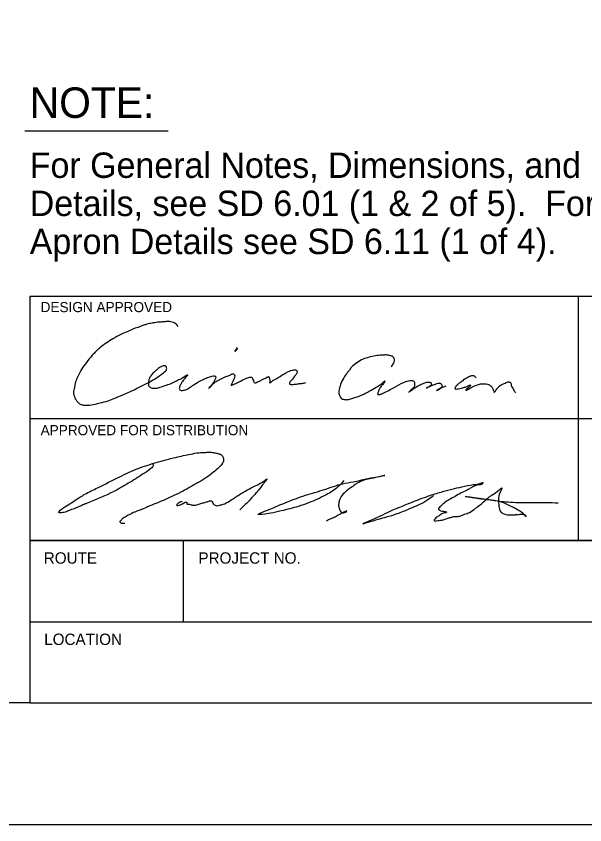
# Model space of a CAD drawing. Extents: x -0.08 to 2.83, y -0.03 to 1.92.
# Drawn here: x 2.0669 to 2.3584, y 0 to 0.4144 of the extents above; entities that cross this region are included whole.
import ezdxf

# ---------------------------------------------------------------- set-up
doc = ezdxf.new("R2010")
doc.units = 0
for name, color, linetype in [('55', 7, 'Continuous'), ('57', 7, 'Continuous'), ('63', 7, 'Continuous')]:
    doc.layers.add(name, color=color, linetype=linetype)

msp = doc.modelspace()

# ---------------------------------------------------------------- linework, layer by layer
at = {"layer": '55'}
for points in [[(2.1500069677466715, 0.25542621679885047), (2.147577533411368, 0.2574101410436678), (2.1461672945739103, 0.2578491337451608), (2.1442302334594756, 0.2579375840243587), (2.1422467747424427, 0.25775571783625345), (2.140196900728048, 0.2576109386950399), (2.1372155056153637, 0.25720220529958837), (2.134606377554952, 0.2567424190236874), (2.1331233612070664, 0.25633337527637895), (2.1313915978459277, 0.25569730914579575), (2.130904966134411, 0.2554811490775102), (2.1278956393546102, 0.254460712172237), (2.1248414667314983, 0.2532039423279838), (2.1206008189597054, 0.2513202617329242), (2.1164790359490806, 0.24905655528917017), (2.112972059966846, 0.24683288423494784), (2.109866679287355, 0.24445465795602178), (2.1058774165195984, 0.24061839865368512), (2.1029880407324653, 0.2370043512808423), (2.1005930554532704, 0.23377638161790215), (2.0985717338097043, 0.22978215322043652), (2.097353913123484, 0.22697719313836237), (2.096580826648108, 0.22347083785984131), (2.0963238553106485, 0.22082632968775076), (2.096499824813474, 0.22020531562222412), (2.096808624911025, 0.2195101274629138), (2.097231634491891, 0.21833296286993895), (2.0979975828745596, 0.21720824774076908), (2.0993643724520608, 0.21581771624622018), (2.101004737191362, 0.21519794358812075), (2.1035519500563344, 0.21504757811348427), (2.1073598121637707, 0.21565695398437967), (2.1099411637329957, 0.2162542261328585), (2.113988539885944, 0.21726131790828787), (2.1174574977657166, 0.2186523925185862), (2.12240256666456, 0.22067417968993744), (2.128578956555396, 0.22355921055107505), (2.134136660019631, 0.22631924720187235), (2.1412178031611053, 0.2307464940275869), (2.1435522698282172, 0.23264910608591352), (2.143802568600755, 0.2329101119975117), (2.1440344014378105, 0.23351250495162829), (2.144034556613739, 0.23426169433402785), (2.1439512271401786, 0.23467415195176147), (2.1436624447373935, 0.2350619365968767), (2.143056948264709, 0.2352258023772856), (2.142306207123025, 0.2351919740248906), (2.1413762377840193, 0.23496200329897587), (2.1401480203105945, 0.23416672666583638), (2.138306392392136, 0.232616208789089), (2.136596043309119, 0.23095753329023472), (2.1355020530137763, 0.2293728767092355), (2.134851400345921, 0.22780203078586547), (2.1346858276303, 0.22641336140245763), (2.1347103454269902, 0.22545871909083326), (2.134988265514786, 0.22483304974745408), (2.1355087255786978, 0.2242984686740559), (2.136138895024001, 0.22392914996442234), (2.1371197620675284, 0.22378219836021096), (2.13865212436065, 0.22378033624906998), (2.1406140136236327, 0.22423562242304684), (2.1439014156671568, 0.22537957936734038), (2.1470884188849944, 0.22656217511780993), (2.1496359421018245, 0.22791018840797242), (2.1523502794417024, 0.2291824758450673), (2.154800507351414, 0.23063709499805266), (2.153210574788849, 0.22863237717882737), (2.1527794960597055, 0.22814124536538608), (2.1521227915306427, 0.22718365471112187), (2.1512373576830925, 0.22569163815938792), (2.150548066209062, 0.2240203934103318), (2.1506158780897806, 0.2232681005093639), (2.151134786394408, 0.2226995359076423), (2.151710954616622, 0.22263917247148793), (2.153527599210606, 0.2228967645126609), (2.154917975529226, 0.22351436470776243), (2.1573064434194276, 0.2251080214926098), (2.159972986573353, 0.22682519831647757), (2.1627630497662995, 0.22826429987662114), (2.1651266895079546, 0.22931422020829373), (2.1671998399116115, 0.22996875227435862), (2.1687692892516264, 0.23003330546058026), (2.1688534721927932, 0.23001243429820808), (2.1690542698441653, 0.22993515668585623), (2.1691631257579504, 0.22970883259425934), (2.1692093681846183, 0.22922995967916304), (2.1690161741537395, 0.2287279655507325), (2.1684628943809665, 0.22742510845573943), (2.1677033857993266, 0.2260805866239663), (2.1656932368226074, 0.22382262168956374), (2.166277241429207, 0.22430677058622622), (2.168280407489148, 0.22641180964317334), (2.1688257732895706, 0.22679555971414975), (2.169879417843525, 0.2274966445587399), (2.171099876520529, 0.22812200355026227), (2.1728085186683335, 0.22899750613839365), (2.174548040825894, 0.22980348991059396), (2.176522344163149, 0.23053064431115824), (2.178045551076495, 0.23107407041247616), (2.178450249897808, 0.23098748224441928), (2.1788394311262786, 0.23056105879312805), (2.1788577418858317, 0.22947048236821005), (2.1783129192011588, 0.22797993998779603), (2.1779551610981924, 0.22723005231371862), (2.1773099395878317, 0.2257781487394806), (2.177159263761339, 0.2254615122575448), (2.177155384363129, 0.2253765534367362), (2.1775307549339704, 0.22539346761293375), (2.1782066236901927, 0.2256520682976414), (2.1789527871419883, 0.22595854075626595), (2.1800318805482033, 0.22647116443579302), (2.18113184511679, 0.22706797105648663), (2.184247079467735, 0.22854330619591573), (2.185947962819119, 0.2292488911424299), (2.187013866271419, 0.22947265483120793), (2.187506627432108, 0.22945015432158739), (2.1876394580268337, 0.2293759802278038), (2.187770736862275, 0.22926782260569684), (2.1880548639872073, 0.2287780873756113), (2.188485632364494, 0.22777084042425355), (2.189192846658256, 0.22647853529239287), (2.1902973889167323, 0.22680269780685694), (2.1916197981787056, 0.22742340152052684), (2.193050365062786, 0.2281753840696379), (2.1947219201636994, 0.2289844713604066), (2.19580334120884, 0.2295480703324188), (2.1961849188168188, 0.22970091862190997), (2.196515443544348, 0.22948149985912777), (2.1967655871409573, 0.22899331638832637), (2.1968118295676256, 0.22851444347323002), (2.196882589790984, 0.22708092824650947), (2.196891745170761, 0.22653564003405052), (2.1969921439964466, 0.22649700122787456), (2.1979407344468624, 0.22713477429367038), (2.200537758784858, 0.228821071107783), (2.203062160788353, 0.23040852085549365), (2.2051616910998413, 0.23164077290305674), (2.2069738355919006, 0.23254560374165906), (2.208390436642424, 0.2329917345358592), (2.2100649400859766, 0.2331195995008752), (2.210599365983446, 0.23289087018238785), (2.2108186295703, 0.23247220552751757), (2.210898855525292, 0.23199178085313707), (2.2108091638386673, 0.23151911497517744), (2.2104043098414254, 0.23085651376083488), (2.2096456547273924, 0.22990357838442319), (2.208306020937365, 0.22815986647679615), (2.2071193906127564, 0.22678376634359), (2.2069895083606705, 0.22617671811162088), (2.2071454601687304, 0.22586310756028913), (2.208498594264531, 0.22566510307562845), (2.2094223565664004, 0.22575913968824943), (2.210551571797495, 0.2258778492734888), (2.211614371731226, 0.22603364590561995), (2.212471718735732, 0.22616476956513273), (2.2141833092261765, 0.2263590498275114), (2.2153898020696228, 0.22667855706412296)], [(2.1798599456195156, 0.2447066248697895), (2.1799895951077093, 0.24418988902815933), (2.179454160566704, 0.24327784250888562), (2.178909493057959, 0.2425364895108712), (2.180163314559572, 0.24389249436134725), (2.180611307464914, 0.24400825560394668)], [(2.2591252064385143, 0.2347190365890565), (2.2602902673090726, 0.23636855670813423), (2.260761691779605, 0.23774326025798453), (2.2607649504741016, 0.23856041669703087), (2.2606198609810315, 0.23911191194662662), (2.260043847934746, 0.23992146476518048), (2.259446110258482, 0.24025524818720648), (2.2583030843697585, 0.24057987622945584), (2.256440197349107, 0.24080115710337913), (2.2542219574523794, 0.24069812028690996), (2.2511432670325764, 0.24039599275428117), (2.2477709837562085, 0.2396305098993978), (2.244797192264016, 0.23864250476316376), (2.2415482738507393, 0.2368497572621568), (2.2388213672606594, 0.23455641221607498), (2.2376964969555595, 0.23304127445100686), (2.2365036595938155, 0.23152924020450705), (2.2348240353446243, 0.2290518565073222), (2.2331689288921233, 0.22561983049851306), (2.2325103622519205, 0.22312987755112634), (2.232303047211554, 0.2215728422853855), (2.232497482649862, 0.22061044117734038), (2.2327545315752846, 0.21990058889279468), (2.233335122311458, 0.2188183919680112), (2.234140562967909, 0.21818566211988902), (2.234983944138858, 0.21801093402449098), (2.236102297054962, 0.21789175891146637), (2.2369565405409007, 0.21795491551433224), (2.2378138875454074, 0.21808603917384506), (2.238987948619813, 0.21844108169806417), (2.241062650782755, 0.21912959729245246), (2.2433829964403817, 0.21997716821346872), (2.245680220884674, 0.22106417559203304), (2.2479125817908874, 0.22222225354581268), (2.2514813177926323, 0.22430688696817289), (2.254075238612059, 0.22592521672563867), (2.2552818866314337, 0.22699391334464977), (2.2559555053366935, 0.22757613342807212), (2.2558040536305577, 0.22724250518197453), (2.2556912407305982, 0.22700927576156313), (2.2544211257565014, 0.2252964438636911), (2.2533286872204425, 0.22374577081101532), (2.252685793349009, 0.22234484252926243), (2.252450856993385, 0.22167448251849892), (2.2522143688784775, 0.2209701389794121), (2.252205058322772, 0.22076623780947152), (2.2522652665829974, 0.22059321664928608), (2.2526344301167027, 0.22047419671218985), (2.252977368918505, 0.22052664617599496), (2.253596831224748, 0.22066863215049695), (2.2550196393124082, 0.22125069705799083), (2.2607388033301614, 0.22419066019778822), (2.2654522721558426, 0.22673383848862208), (2.267319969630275, 0.22736369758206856), (2.268767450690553, 0.2277403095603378), (2.2699908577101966, 0.22768444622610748), (2.270760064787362, 0.22737688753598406), (2.2711059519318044, 0.2267481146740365), (2.271119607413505, 0.2255555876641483), (2.2710175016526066, 0.22481105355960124), (2.270611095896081, 0.22411446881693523), (2.2681900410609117, 0.2218071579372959), (2.2709338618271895, 0.22372513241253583), (2.27398043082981, 0.22556117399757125), (2.276442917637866, 0.2265384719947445), (2.2784341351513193, 0.22689025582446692), (2.279272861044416, 0.22661357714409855), (2.279848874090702, 0.22580402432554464), (2.279768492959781, 0.22553525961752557), (2.2797607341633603, 0.22536534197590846), (2.2794115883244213, 0.22517695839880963), (2.2785989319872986, 0.22453297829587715), (2.2770648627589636, 0.22375166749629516), (2.279715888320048, 0.22512900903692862), (2.281793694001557, 0.22588549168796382), (2.2825568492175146, 0.22619118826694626), (2.284025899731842, 0.22629438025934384), (2.2846931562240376, 0.22599147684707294), (2.2851703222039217, 0.2252545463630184), (2.285145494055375, 0.22471080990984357), (2.2849214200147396, 0.22427833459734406), (2.2839295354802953, 0.22343821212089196), (2.2823537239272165, 0.222488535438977), (2.2853230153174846, 0.22412377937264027), (2.2873344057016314, 0.22491734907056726)], [(2.3026712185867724, 0.22891654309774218), (2.302339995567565, 0.22949356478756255), (2.3017978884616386, 0.2299269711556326), (2.3013113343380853, 0.2300854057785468), (2.3008008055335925, 0.23009169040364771), (2.3003211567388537, 0.23002845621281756), (2.2995657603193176, 0.22989267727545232), (2.2989400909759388, 0.2296147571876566), (2.2977512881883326, 0.2289368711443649), (2.296770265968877, 0.22833463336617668), (2.295817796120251, 0.2276119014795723), (2.294285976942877, 0.2265069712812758), (2.2932091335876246, 0.22567072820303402), (2.2921554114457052, 0.22459504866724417), (2.2918919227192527, 0.22404518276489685), (2.2918045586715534, 0.22362349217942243), (2.2918231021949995, 0.2236566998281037), (2.291985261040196, 0.22347902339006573), (2.292507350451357, 0.22335302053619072), (2.2935987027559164, 0.2233883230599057), (2.2950122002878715, 0.22376648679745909), (2.29628898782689, 0.22413386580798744), (2.2979836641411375, 0.22470351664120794), (2.299324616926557, 0.22535742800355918), (2.2995656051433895, 0.22541453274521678), (2.299764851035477, 0.22530327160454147), (2.2998111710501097, 0.22519899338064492), (2.2997508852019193, 0.22499741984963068), (2.299588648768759, 0.22480050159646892), (2.2983140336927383, 0.22373490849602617), (2.297440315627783, 0.22287236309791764), (2.2973499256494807, 0.2227573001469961), (2.2974325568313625, 0.2227024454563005), (2.2978102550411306, 0.22277033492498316), (2.2988043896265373, 0.22328683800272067), (2.3005725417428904, 0.2243469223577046), (2.3018795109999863, 0.22500238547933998), (2.3039217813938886, 0.22572643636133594), (2.3060983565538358, 0.22603570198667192), (2.3084887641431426, 0.22580736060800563), (2.309493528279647, 0.2254379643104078), (2.3103646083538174, 0.2247511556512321), (2.310914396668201, 0.22411307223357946), (2.311596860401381, 0.22265162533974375), (2.311958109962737, 0.22161349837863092), (2.312603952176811, 0.22233320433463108), (2.3133363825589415, 0.2234576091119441), (2.3143406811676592, 0.22456959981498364), (2.315820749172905, 0.22565986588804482), (2.317557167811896, 0.22639788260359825), (2.3194912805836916, 0.226990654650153), (2.3197600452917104, 0.2269102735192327), (2.3202265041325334, 0.22668464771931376), (2.320701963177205, 0.2251645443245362), (2.3212609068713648, 0.2239811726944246), (2.321890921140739, 0.22286266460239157), (2.322332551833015, 0.2220933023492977), (2.322916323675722, 0.2214536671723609)], [(2.136922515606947, 0.185159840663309), (2.1371105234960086, 0.1844864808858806), (2.1370818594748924, 0.1840234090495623), (2.136805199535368, 0.1834854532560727), (2.1358939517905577, 0.18254654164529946), (2.131948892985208, 0.17981845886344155), (2.128213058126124, 0.17737820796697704), (2.1243688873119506, 0.17504310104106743), (2.11671133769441, 0.17069363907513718), (2.1037354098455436, 0.1650190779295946), (2.102285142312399, 0.1644279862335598), (2.099987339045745, 0.1633971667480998), (2.0937609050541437, 0.16091967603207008), (2.091388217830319, 0.16013685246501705), (2.0901811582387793, 0.15994086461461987), (2.0891859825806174, 0.15985480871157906), (2.0890431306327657, 0.15988826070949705), (2.088754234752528, 0.1601686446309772), (2.0888583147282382, 0.1603481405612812), (2.089137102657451, 0.16074377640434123), (2.0900133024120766, 0.16164657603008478), (2.093607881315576, 0.16401353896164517), (2.097096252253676, 0.16634332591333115), (2.1021039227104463, 0.16940758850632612), (2.108637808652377, 0.17274378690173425), (2.119977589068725, 0.17835829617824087), (2.1292027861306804, 0.18258884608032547), (2.1386239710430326, 0.1856123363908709), (2.148761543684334, 0.18832624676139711), (2.1564234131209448, 0.19000667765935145), (2.1605411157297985, 0.190708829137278), (2.1640969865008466, 0.19090434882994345), (2.1663741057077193, 0.19093839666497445), (2.168298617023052, 0.19075364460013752), (2.1702273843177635, 0.19028425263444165), (2.171801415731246, 0.18973838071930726), (2.172450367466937, 0.18917867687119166), (2.172812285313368, 0.18877482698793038), (2.173071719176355, 0.18808474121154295), (2.173241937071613, 0.18741111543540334), (2.1732305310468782, 0.18698388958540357), (2.173168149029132, 0.1863957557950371), (2.1730497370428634, 0.1859847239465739), (2.1727207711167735, 0.18537481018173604), (2.1719537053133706, 0.18431349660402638), (2.170708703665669, 0.1830848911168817), (2.1680747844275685, 0.18073229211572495), (2.1645906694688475, 0.17811786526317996), (2.160535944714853, 0.17558387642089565), (2.15564854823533, 0.17280611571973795), (2.152454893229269, 0.17099676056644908), (2.1477549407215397, 0.16877341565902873), (2.1451217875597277, 0.1675596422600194), (2.1395713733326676, 0.1650922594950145), (2.135503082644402, 0.1634655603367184), (2.1319318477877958, 0.16191746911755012), (2.127685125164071, 0.16032368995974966), (2.1248238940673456, 0.15889297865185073), (2.122776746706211, 0.15775914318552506), (2.1218256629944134, 0.1571043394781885), (2.1213148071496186, 0.15675861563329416), (2.120858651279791, 0.1563247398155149), (2.120456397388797, 0.15585608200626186), (2.1201247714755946, 0.15542406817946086), (2.120107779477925, 0.15537043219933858), (2.120109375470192, 0.15526369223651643), (2.120200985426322, 0.15508712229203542), (2.1203642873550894, 0.1548760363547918), (2.1206157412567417, 0.15471965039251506), (2.121151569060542, 0.1545853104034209), (2.121560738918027, 0.15459142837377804), (2.1223610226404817, 0.15462118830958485), (2.1226634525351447, 0.1546257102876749)], [(2.2349098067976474, 0.17650908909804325), (2.2318638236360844, 0.1731538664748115), (2.225837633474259, 0.1691846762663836), (2.2167898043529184, 0.16499236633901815), (2.2115850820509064, 0.16320632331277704), (2.2027581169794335, 0.16090347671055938), (2.197473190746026, 0.159721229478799), (2.192926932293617, 0.15911943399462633), (2.190720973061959, 0.15908645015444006), (2.1923459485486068, 0.15989368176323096), (2.1973690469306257, 0.16192612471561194), (2.2051498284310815, 0.1651742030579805), (2.2151657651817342, 0.16888275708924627), (2.2249788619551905, 0.17187651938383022), (2.2341881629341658, 0.17479007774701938), (2.239653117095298, 0.17583266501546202), (2.246393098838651, 0.17728578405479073), (2.2531352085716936, 0.17859658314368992), (2.2557617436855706, 0.17906291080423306), (2.250051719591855, 0.17774974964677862), (2.24375994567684, 0.17607201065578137), (2.2429822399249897, 0.17572229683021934), (2.242027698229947, 0.17529876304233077), (2.2406717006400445, 0.17435320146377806), (2.2381891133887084, 0.17259006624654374), (2.235849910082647, 0.1707578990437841), (2.2335035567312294, 0.16821386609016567), (2.232811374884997, 0.16690455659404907), (2.232356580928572, 0.1651895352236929), (2.232245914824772, 0.16307039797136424), (2.2324705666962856, 0.16232641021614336), (2.2327047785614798, 0.16153808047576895), (2.233272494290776, 0.16046113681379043), (2.2337408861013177, 0.16007667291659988), (2.2342602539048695, 0.1598531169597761), (2.2351476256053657, 0.16000873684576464), (2.23578407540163, 0.16028516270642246), (2.236397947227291, 0.16088154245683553), (2.2354779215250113, 0.16052970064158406), (2.2335178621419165, 0.15952172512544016), (2.2319831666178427, 0.15862687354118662), (2.230924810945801, 0.1580060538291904), (2.2285914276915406, 0.15697470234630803), (2.227000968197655, 0.15623916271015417), (2.2260658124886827, 0.15570915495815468)], [(2.1521481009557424, 0.16533369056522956), (2.151646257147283, 0.16557530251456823), (2.15086562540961, 0.1654212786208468), (2.1497026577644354, 0.16465654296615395), (2.14917693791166, 0.16411486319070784), (2.1491811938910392, 0.1638302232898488), (2.1495046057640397, 0.16362153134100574), (2.150425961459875, 0.16388442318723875), (2.151134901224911, 0.16407296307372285), (2.1524789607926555, 0.16462687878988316), (2.153571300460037, 0.1653549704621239), (2.154032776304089, 0.16543304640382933), (2.154175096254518, 0.1654351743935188), (2.154428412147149, 0.1651542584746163), (2.1544018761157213, 0.16454886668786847), (2.154761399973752, 0.1643051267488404), (2.155437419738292, 0.1643152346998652), (2.156187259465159, 0.16414850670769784), (2.156972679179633, 0.16398231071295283), (2.1577230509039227, 0.16378000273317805), (2.1589322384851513, 0.1638336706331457), (2.1601010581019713, 0.16420702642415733), (2.1621206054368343, 0.1648066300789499), (2.164033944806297, 0.16536905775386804), (2.1656642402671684, 0.16582048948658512), (2.167119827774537, 0.16605578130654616), (2.1676700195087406, 0.16496078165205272), (2.1680359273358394, 0.16429008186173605), (2.1688967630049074, 0.16384030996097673), (2.1700411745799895, 0.16346595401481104), (2.171281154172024, 0.1638403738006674), (2.1729831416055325, 0.1642572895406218), (2.1761969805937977, 0.16590680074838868), (2.180003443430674, 0.16838369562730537), (2.1850822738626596, 0.17144902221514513), (2.190873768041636, 0.1744538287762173), (2.1936978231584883, 0.17599074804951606), (2.195582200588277, 0.17730008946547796), (2.1940804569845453, 0.17539147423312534), (2.1936083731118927, 0.17483280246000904), (2.192997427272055, 0.1740407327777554), (2.191584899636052, 0.17211565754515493), (2.1903624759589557, 0.170567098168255), (2.1880511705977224, 0.16805917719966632), (2.1862833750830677, 0.1660932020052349), (2.1836181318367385, 0.16345543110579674), (2.181637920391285, 0.16141510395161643)], [(2.280747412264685, 0.16875122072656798), (2.2779690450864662, 0.16653881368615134), (2.2736633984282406, 0.16412563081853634), (2.268253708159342, 0.16176711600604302), (2.262062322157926, 0.15932573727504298), (2.2565718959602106, 0.1576065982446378), (2.252424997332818, 0.15647695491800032), (2.2445926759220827, 0.15429574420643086), (2.249259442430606, 0.15635844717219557), (2.252618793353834, 0.15779660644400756), (2.257245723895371, 0.16014341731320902), (2.2625847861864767, 0.16246528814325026), (2.269907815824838, 0.16538623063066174), (2.278223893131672, 0.16853554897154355), (2.2848130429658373, 0.17055581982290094), (2.2903071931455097, 0.17202589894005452), (2.2953781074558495, 0.17324053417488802), (2.3010910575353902, 0.17435800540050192), (2.305879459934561, 0.17542606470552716), (2.306056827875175, 0.17546430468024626), (2.306060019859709, 0.17525082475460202), (2.3031584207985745, 0.17413980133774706), (2.3008956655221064, 0.17314509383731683), (2.2992367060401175, 0.1722305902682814), (2.298072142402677, 0.1715725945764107), (2.2950685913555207, 0.1701397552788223), (2.2918929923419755, 0.16831287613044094), (2.2890694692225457, 0.16674037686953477), (2.2867079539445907, 0.16521037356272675), (2.284529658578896, 0.16332723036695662), (2.2836529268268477, 0.16246001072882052), (2.2833396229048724, 0.16199268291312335), (2.28345221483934, 0.1616028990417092), (2.283921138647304, 0.1611828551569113), (2.2853146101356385, 0.16081222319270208), (2.28727736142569, 0.16045010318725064), (2.287491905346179, 0.16038213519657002), (2.287529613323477, 0.16024034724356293), (2.2865742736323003, 0.1598701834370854), (2.2841017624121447, 0.1586232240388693), (2.2824794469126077, 0.15763809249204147), (2.2816016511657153, 0.1568420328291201), (2.2812193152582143, 0.15623132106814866), (2.2811869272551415, 0.15601730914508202), (2.281332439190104, 0.15580595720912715), (2.282257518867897, 0.1558197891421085), (2.285170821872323, 0.15614805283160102), (2.2867299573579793, 0.1565984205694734), (2.288889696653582, 0.1573424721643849), (2.2904488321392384, 0.15779283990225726), (2.292260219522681, 0.15803345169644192), (2.2943211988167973, 0.15824220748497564), (2.2966922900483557, 0.15913177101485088), (2.2993108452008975, 0.16013179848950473), (2.3023759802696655, 0.1622061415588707), (2.3047682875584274, 0.16405689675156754), (2.3094063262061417, 0.16804091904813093), (2.3110259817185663, 0.16920395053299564), (2.314337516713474, 0.17145991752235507), (2.315813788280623, 0.17269198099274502), (2.314511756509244, 0.16932724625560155), (2.3141284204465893, 0.16640330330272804), (2.3143887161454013, 0.1632754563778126), (2.3152119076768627, 0.16058308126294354), (2.3169378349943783, 0.15939889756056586), (2.3206477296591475, 0.15881378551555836), (2.322852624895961, 0.15891792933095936), (2.3230825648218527, 0.15901033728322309), (2.3232933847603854, 0.15919142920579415), (2.3235347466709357, 0.1591149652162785), (2.323643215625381, 0.1590009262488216), (2.3246742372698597, 0.15906972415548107), (2.3256317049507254, 0.15929756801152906), (2.326988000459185, 0.1590331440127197), (2.3280416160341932, 0.1581858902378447), (2.3281674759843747, 0.15809880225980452), (2.3282472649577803, 0.1581177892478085), (2.32824606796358, 0.1581978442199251), (2.3281279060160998, 0.1583651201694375), (2.327209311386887, 0.15910762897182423), (2.3270110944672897, 0.1592737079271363), (2.3250582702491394, 0.160756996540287), (2.3239170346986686, 0.16151397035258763), (2.3203223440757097, 0.16331969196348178), (2.316272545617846, 0.16521647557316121), (2.315003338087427, 0.16560675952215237), (2.3128621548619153, 0.16600179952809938), (2.3097948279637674, 0.1664541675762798), (2.306016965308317, 0.1668247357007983), (2.302093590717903, 0.16740665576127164), (2.2990262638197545, 0.16785902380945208), (2.297312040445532, 0.16826044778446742), (2.3028739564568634, 0.1675784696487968), (2.311040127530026, 0.1664727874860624), (2.3189381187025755, 0.16545206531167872), (2.324421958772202, 0.16523156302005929), (2.330988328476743, 0.1652051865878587), (2.3431965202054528, 0.16510302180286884), (2.3447272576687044, 0.16507252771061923)]]:
    msp.add_spline(points, degree=3, dxfattribs=at)
at = {"layer": '57'}
msp.add_line((2.0713113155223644, 0.35560013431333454), (2.144774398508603, 0.35560013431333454), dxfattribs=at)
msp.add_line((2.0713113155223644, 0.35560013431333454), (2.144774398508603, 0.35560013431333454), dxfattribs=at)
at = {"layer": '63'}
for p, q in [((2.729175, 0.270775), (2.073866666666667, 0.270775)), ((2.073866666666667, 0.270775), (2.073866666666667, 0.06244166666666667)), ((2.354925, 0.270775), (2.354925, 0.14577500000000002)), ((2.073866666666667, 0.20827500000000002), (2.729175, 0.20827500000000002)), ((2.073866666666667, 0.2064666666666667), (2.073866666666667, 0.2064666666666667)), ((2.073866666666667, 0.14577500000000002), (2.729175, 0.14577500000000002)), ((2.0890750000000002, 0.145825), (2.0893083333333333, 0.145825)), ((2.152655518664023, 0.10410833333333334), (2.152655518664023, 0.14577500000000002)), ((2.237416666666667, 0.145825), (2.237416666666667, 0.145825)), ((2.073866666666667, 0.1439666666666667), (2.073866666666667, 0.1439666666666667)), ((2.073866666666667, 0.10410833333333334), (2.5625083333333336, 0.10410833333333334)), ((2.073866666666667, 0.06244166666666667), (2.729175, 0.06244166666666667)), ((2.8333333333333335, 0), (0, 0))]:
    msp.add_line(p, q, dxfattribs=at)
msp.add_lwpolyline([(0.16667500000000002, 0.06244166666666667), (0.16667500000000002, 1.770775), (2.729175, 1.770775), (2.729175, 0.10410833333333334), (2.5625083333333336, 0.10410833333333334), (2.5625083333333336, 0.14577500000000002), (2.073866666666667, 0.14577500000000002), (2.073866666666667, 0.06244166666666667)], close=True, dxfattribs=at)

# ---------------------------------------------------------------- texts
at = {"layer": '55'}
for s, p in [('DESIGN APPROVED', (2.079441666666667, 0.2627416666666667)), ('APPROVED FOR DISTRIBUTION', (2.079441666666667, 0.19965833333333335))]:
    msp.add_text(s, height=0.0052083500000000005, dxfattribs=at).set_placement(p)
at = {"layer": '57'}
for s, height, p in [('NOTE:', 0.015625, (2.073866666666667, 0.3623067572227)), ('NOTE:', 0.015625, (2.073866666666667, 0.3623067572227)), ('For General Notes, Dimensions, and additional', 0.013020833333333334, (2.073866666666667, 0.3315448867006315)), ('For General Notes, Dimensions, and additional', 0.013020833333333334, (2.073866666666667, 0.3315448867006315)), ('Details, see SD 6.01 (1 & 2 of 5).  For Outlet', 0.013020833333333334, (2.073866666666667, 0.3120136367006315)), ('Details, see SD 6.01 (1 & 2 of 5).  For Outlet', 0.013020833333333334, (2.073866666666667, 0.3120136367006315)), ('Apron Details see SD 6.11 (1 of 4).', 0.013020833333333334, (2.073866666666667, 0.2924823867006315)), ('Apron Details see SD 6.11 (1 of 4).', 0.013020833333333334, (2.073866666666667, 0.2924823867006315))]:
    msp.add_text(s, height=height, dxfattribs=at).set_placement(p)
at = {"layer": '63'}
for s, p in [('ROUTE', (2.0810500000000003, 0.13383333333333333)), ('PROJECT NO.', (2.160343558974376, 0.13383333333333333)), ('LOCATION', (2.081284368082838, 0.09216666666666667))]:
    msp.add_text(s, height=0.0058333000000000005, dxfattribs=at).set_placement(p)

doc.saveas('drawing.dxf')
